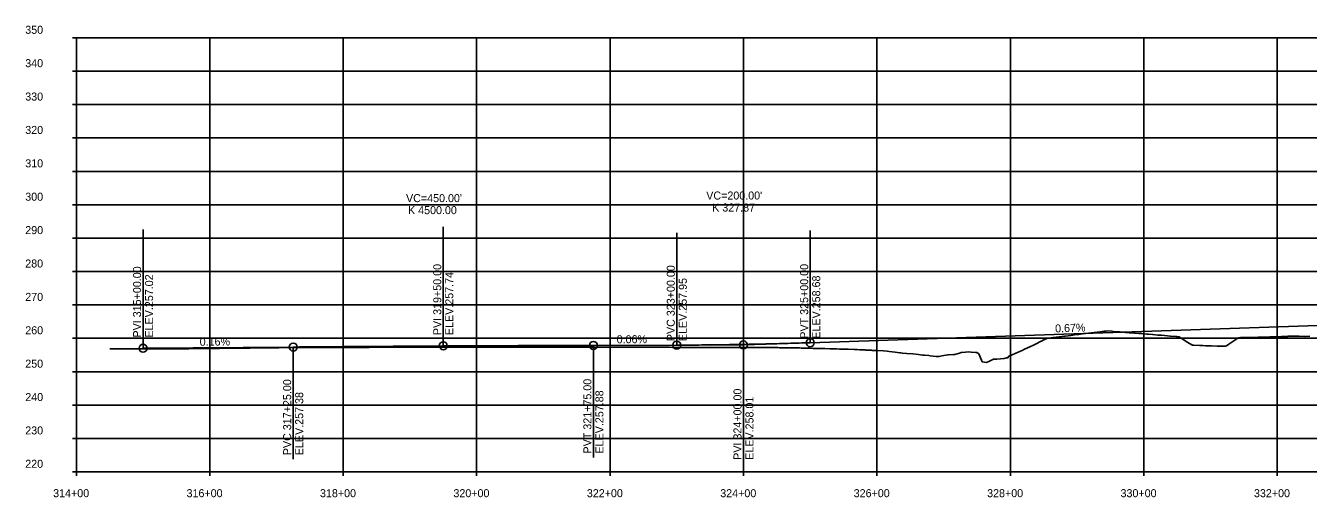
# Model space of a CAD drawing. Extents: x 880555 to 887700, y 1561392 to 1563161.
# Drawn here: x 880555 to 882477, y 1562454 to 1563161 of the extents above; entities that cross this region are included whole.
import ezdxf

# ---------------------------------------------------------------- set-up
doc = ezdxf.new("R2010")
doc.units = 0
for name, color, linetype in [('1', 7, 'Continuous'), ('30', 7, 'Continuous'), ('37', 7, 'Continuous'), ('56', 7, 'Continuous'), ('63', 7, 'Continuous'), ('R_Exist Surface', 7, 'Continuous')]:
    doc.layers.add(name, color=color, linetype=linetype)

msp = doc.modelspace()

# ---------------------------------------------------------------- linework, layer by layer
at = {"layer": '1'}
for p, q in [((881068.1, 1562680.4), (881180.6, 1562681.3)), ((881180.6, 1562681.3), (881293.1, 1562681.6)), ((881580.6, 1562682.5), (881630.6, 1562682.6)), ((881630.6, 1562682.6), (881680.6, 1562684.3))]:
    msp.add_line(p, q, dxfattribs=at)
at = {"layer": '37'}
for p, q in [((880624.6, 1563142.6), (880630.6, 1563142.6)), ((880624.6, 1563142.6), (880630.6, 1563142.6)), ((880630.6, 1562492.6), (880630.6, 1563142.6)), ((880630.6, 1563142.6), (887630.6, 1563142.6)), ((880630.6, 1563142.6), (887630.6, 1563142.6)), ((880830.6, 1562492.6), (880830.6, 1563142.6)), ((881030.6, 1562492.6), (881030.6, 1563142.6)), ((881230.6, 1562492.6), (881230.6, 1563142.6)), ((881430.6, 1562492.6), (881430.6, 1563142.6)), ((881630.6, 1562492.6), (881630.6, 1563142.6)), ((881830.6, 1562492.6), (881830.6, 1563142.6)), ((882030.6, 1562492.6), (882030.6, 1563142.6)), ((882230.6, 1562492.6), (882230.6, 1563142.6)), ((882430.6, 1562492.6), (882430.6, 1563142.6)), ((880624.6, 1563092.6), (880630.6, 1563092.6)), ((880630.6, 1563092.6), (887630.6, 1563092.6)), ((880624.6, 1563042.6), (880630.6, 1563042.6)), ((880630.6, 1563042.6), (887630.6, 1563042.6)), ((880624.6, 1562992.6), (880630.6, 1562992.6)), ((880630.6, 1562992.6), (887630.6, 1562992.6)), ((880624.6, 1562942.6), (880630.6, 1562942.6)), ((880630.6, 1562942.6), (887630.6, 1562942.6)), ((880624.6, 1562892.6), (880630.6, 1562892.6)), ((880630.6, 1562892.6), (887630.6, 1562892.6)), ((880624.6, 1562842.6), (880630.6, 1562842.6)), ((880630.6, 1562842.6), (887630.6, 1562842.6)), ((880624.6, 1562792.6), (880630.6, 1562792.6)), ((880630.6, 1562792.6), (887630.6, 1562792.6)), ((880624.6, 1562742.6), (880630.6, 1562742.6)), ((880630.6, 1562742.6), (887630.6, 1562742.6)), ((880624.6, 1562692.6), (880630.6, 1562692.6)), ((880630.6, 1562692.6), (887630.6, 1562692.6)), ((880624.6, 1562642.6), (880630.6, 1562642.6)), ((880630.6, 1562642.6), (887630.6, 1562642.6)), ((880624.6, 1562592.6), (880630.6, 1562592.6)), ((880630.6, 1562592.6), (887630.6, 1562592.6)), ((880624.6, 1562542.6), (880630.6, 1562542.6)), ((880630.6, 1562542.6), (887630.6, 1562542.6)), ((880624.6, 1562492.6), (880630.6, 1562492.6)), ((880630.6, 1562492.6), (887630.6, 1562492.6)), ((880630.6, 1562486.6), (880630.6, 1562492.6)), ((880830.6, 1562486.6), (880830.6, 1562492.6)), ((881030.6, 1562486.6), (881030.6, 1562492.6)), ((881230.6, 1562486.6), (881230.6, 1562492.6)), ((881430.6, 1562486.6), (881430.6, 1562492.6)), ((881630.6, 1562486.6), (881630.6, 1562492.6)), ((881830.6, 1562486.6), (881830.6, 1562492.6)), ((882030.6, 1562486.6), (882030.6, 1562492.6)), ((882230.6, 1562486.6), (882230.6, 1562492.6)), ((882430.6, 1562486.6), (882430.6, 1562492.6))]:
    msp.add_line(p, q, dxfattribs=at)
at = {"layer": '56'}
for p, q in [((880730.6, 1562687.7), (880730.6, 1562855.7)), ((881180.6, 1562691.3), (881180.6, 1562859.3)), ((881530.6, 1562682.3), (881530.6, 1562850.3)), ((881730.6, 1562686), (881730.6, 1562854)), ((881730.6, 1562686), (882520.6, 1562712.5)), ((880730.6, 1562677.7), (880730.6, 1562687.7)), ((880730.6, 1562677.7), (880955.6, 1562679.5)), ((880955.6, 1562679.5), (880955.6, 1562511.5)), ((881180.6, 1562681.3), (881180.6, 1562691.3)), ((881405.6, 1562682), (881530.6, 1562682.3)), ((881405.6, 1562682), (881405.6, 1562514)), ((881630.6, 1562682.6), (881630.6, 1562672.6)), ((881630.6, 1562672.6), (881630.6, 1562504.6))]:
    msp.add_line(p, q, dxfattribs=at)
for points in [[(880955.6, 1562679.5), (880965, 1562679.6), (880974.4, 1562679.6), (880983.7, 1562679.7), (880993.1, 1562679.8), (881002.5, 1562679.9), (881011.9, 1562679.9), (881021.2, 1562680), (881030.6, 1562680.1), (881040, 1562680.1), (881049.4, 1562680.2), (881058.7, 1562680.3), (881068.1, 1562680.3), (881077.5, 1562680.4), (881086.9, 1562680.4), (881096.2, 1562680.5), (881105.6, 1562680.6), (881115, 1562680.6), (881124.4, 1562680.7), (881133.7, 1562680.7), (881143.1, 1562680.8), (881152.5, 1562680.9), (881161.9, 1562680.9), (881171.2, 1562681), (881190, 1562681.1), (881199.4, 1562681.1), (881208.7, 1562681.2), (881218.1, 1562681.2), (881227.5, 1562681.3), (881236.9, 1562681.3), (881246.2, 1562681.3), (881255.6, 1562681.4), (881265, 1562681.4), (881274.4, 1562681.5), (881283.7, 1562681.5), (881293.1, 1562681.6), (881302.5, 1562681.6), (881311.9, 1562681.6), (881321.2, 1562681.7), (881330.6, 1562681.7), (881340, 1562681.7), (881349.4, 1562681.8), (881358.7, 1562681.8), (881368.1, 1562681.8), (881377.5, 1562681.9), (881386.9, 1562681.9), (881396.2, 1562681.9), (881405.6, 1562682)], [(881530.6, 1562682.3), (881534.8, 1562682.4), (881538.9, 1562682.4), (881543.1, 1562682.4), (881547.3, 1562682.4), (881551.4, 1562682.4), (881555.6, 1562682.5), (881559.8, 1562682.5), (881563.9, 1562682.5), (881568.1, 1562682.6), (881572.3, 1562682.6), (881576.4, 1562682.6), (881580.6, 1562682.7), (881584.8, 1562682.7), (881588.9, 1562682.8), (881593.1, 1562682.8), (881597.3, 1562682.9), (881601.4, 1562682.9), (881605.6, 1562683), (881609.8, 1562683.1), (881613.9, 1562683.1), (881618.1, 1562683.2), (881622.3, 1562683.3), (881626.4, 1562683.3), (881634.8, 1562683.5), (881638.9, 1562683.6), (881643.1, 1562683.6), (881647.3, 1562683.7), (881651.4, 1562683.8), (881655.6, 1562683.9), (881659.8, 1562684), (881663.9, 1562684.1), (881668.1, 1562684.2), (881672.3, 1562684.3), (881676.4, 1562684.4), (881680.6, 1562684.5), (881684.8, 1562684.6), (881688.9, 1562684.7), (881693.1, 1562684.8), (881697.3, 1562685), (881701.4, 1562685.1), (881705.6, 1562685.2), (881709.8, 1562685.3), (881713.9, 1562685.5), (881718.1, 1562685.6), (881722.3, 1562685.7), (881726.4, 1562685.9), (881730.6, 1562686)]]:
    msp.add_lwpolyline(points, dxfattribs=at)
for centre in [(880730.6, 1562677.7), (880955.6, 1562679.5), (881180.6, 1562681.3), (881405.6, 1562682), (881530.6, 1562682.3), (881630.6, 1562682.6), (881730.6, 1562686)]:
    msp.add_circle(centre, 6, dxfattribs=at)
at = {"layer": 'R_Exist Surface'}
msp.add_lwpolyline([(880680.6, 1562676.7), (880693.7, 1562676.7), (880694.3, 1562676.7), (880694.3, 1562676.7), (880697.4, 1562676.7), (880707.8, 1562676.8), (880709.1, 1562676.8), (880709.3, 1562676.8), (880709.3, 1562676.8), (880710, 1562676.8), (880724.3, 1562676.9), (880724.3, 1562676.9), (880731.2, 1562676.9), (880739.3, 1562676.8), (880739.3, 1562676.8), (880740.7, 1562676.9), (880754.3, 1562676.9), (880754.3, 1562676.9), (880767.7, 1562676.9), (880769.3, 1562676.9), (880769.8, 1562676.9), (880784.3, 1562676.8), (880784.3, 1562676.8), (880798.7, 1562676.9), (880799.3, 1562676.9), (880813.6, 1562677.1), (880814.3, 1562677.1), (880828.1, 1562677.3), (880829.3, 1562677.3), (880829.3, 1562677.3), (880843.7, 1562677.4), (880844.3, 1562677.4), (880845.2, 1562677.4), (880859.3, 1562677.6), (880859.5, 1562677.6), (880874.3, 1562677.8), (880874.3, 1562677.8), (880888.6, 1562677.9), (880889.3, 1562677.9), (880889.3, 1562677.9), (880890, 1562677.9), (880891.3, 1562677.9), (880904.3, 1562678.1), (880904.3, 1562678.1), (880914.2, 1562678.3), (880919.3, 1562678.3), (880919.3, 1562678.3), (880926.9, 1562678.4), (880934.3, 1562678.5), (880934.3, 1562678.5), (880934.6, 1562678.6), (880949.3, 1562678.8), (880949.9, 1562678.8), (880964.3, 1562678.8), (880964.3, 1562678.8), (880977.2, 1562678.9), (880979.3, 1562678.9), (880979.3, 1562678.9), (880993.7, 1562679), (880994.3, 1562679), (881008.8, 1562678.9), (881009.3, 1562678.9), (881009.8, 1562678.9), (881024.3, 1562678.9), (881024.3, 1562678.9), (881026.1, 1562678.9), (881039.3, 1562679), (881040.5, 1562679), (881054.3, 1562678.9), (881054.3, 1562678.9), (881060.7, 1562679), (881069.3, 1562679), (881069.3, 1562679), (881077.4, 1562679.1), (881084.3, 1562679.2), (881084.3, 1562679.2), (881090.6, 1562679.3), (881099.3, 1562679.3), (881101.4, 1562679.3), (881114.3, 1562679.4), (881114.3, 1562679.4), (881119.3, 1562679.4), (881129.3, 1562679.4), (881129.3, 1562679.4), (881132.4, 1562679.4), (881144.3, 1562679.3), (881144.3, 1562679.4), (881157.5, 1562679.4), (881159.3, 1562679.4), (881164.2, 1562679.3), (881165.8, 1562679.3), (881173, 1562679.3), (881174.4, 1562679.3), (881174.4, 1562679.3), (881181.8, 1562679.3), (881187.2, 1562679.3), (881189.4, 1562679.3), (881189.4, 1562679.3), (881190.5, 1562679.3), (881191.1, 1562679.3), (881199.3, 1562679.3), (881204.4, 1562679.3), (881204.4, 1562679.3), (881206.5, 1562679.3), (881208.1, 1562679.3), (881211.8, 1562679.3), (881216.9, 1562679.4), (881219.4, 1562679.4), (881225.7, 1562679.4), (881231, 1562679.4), (881234.4, 1562679.4), (881234.4, 1562679.4), (881235.9, 1562679.4), (881243.2, 1562679.4), (881249.4, 1562679.5), (881252, 1562679.5), (881258.9, 1562679.5), (881260.8, 1562679.5), (881264.5, 1562679.5), (881269.6, 1562679.4), (881271.3, 1562679.4), (881278.3, 1562679.5), (881279.5, 1562679.5), (881279.5, 1562679.5), (881286.2, 1562679.4), (881287.1, 1562679.4), (881294.5, 1562679.4), (881295.9, 1562679.4), (881304.7, 1562679.3), (881306.5, 1562679.3), (881309.5, 1562679.3), (881309.5, 1562679.3), (881312.4, 1562679.2), (881313.5, 1562679.2), (881322.2, 1562679.2), (881324.5, 1562679.2), (881326.2, 1562679.2), (881331, 1562679.1), (881339.5, 1562679.1), (881339.8, 1562679.1), (881348.6, 1562679.2), (881351.9, 1562679.2), (881354.6, 1562679.2), (881357.4, 1562679.2), (881357.5, 1562679.2), (881366.1, 1562679.2), (881369.6, 1562679.2), (881373.3, 1562679.2), (881374.9, 1562679.3), (881383.7, 1562679.3), (881384.6, 1562679.3), (881392.5, 1562679.3), (881399, 1562679.3), (881399.6, 1562679.3), (881400.3, 1562679.3), (881401.3, 1562679.3), (881410, 1562679.2), (881414.7, 1562679.2), (881418.8, 1562679.2), (881421.6, 1562679.2), (881427.6, 1562679.3), (881429.7, 1562679.3), (881436.4, 1562679.3), (881437.2, 1562679.3), (881444.7, 1562679.3), (881445.2, 1562679.3), (881453.9, 1562679.3), (881458.3, 1562679.3), (881459.7, 1562679.3), (881460.9, 1562679.3), (881462.7, 1562679.3), (881471.5, 1562679.3), (881474.7, 1562679.3), (881480.3, 1562679.3), (881489.1, 1562679.2), (881489.1, 1562679.2), (881489.7, 1562679.2), (881490, 1562679.2), (881497.8, 1562679.2), (881504.7, 1562679.2), (881505, 1562679.2), (881505.5, 1562679.2), (881506.6, 1562679.2), (881514.5, 1562679.1), (881515.4, 1562679.1), (881519.7, 1562679.1), (881524.2, 1562679), (881530.3, 1562679), (881533, 1562679), (881534.7, 1562679), (881541.7, 1562679), (881545.6, 1562679), (881549.7, 1562679), (881550.5, 1562679), (881551, 1562679), (881553.8, 1562679), (881559.3, 1562678.9), (881564.7, 1562678.8), (881564.7, 1562678.8), (881567.5, 1562678.8), (881568.1, 1562678.8), (881570.3, 1562678.8), (881572.7, 1562678.8), (881574.6, 1562678.8), (881576.9, 1562678.8), (881579.8, 1562678.9), (881585.6, 1562678.9), (881588.5, 1562678.9), (881594.4, 1562678.9), (881594.8, 1562678.9), (881603.2, 1562678.9), (881606.2, 1562678.9), (881609.7, 1562678.8), (881612, 1562678.8), (881614, 1562678.8), (881620.8, 1562678.7), (881624.7, 1562678.7), (881627.8, 1562678.7), (881629.5, 1562678.7), (881638.3, 1562678.7), (881639.8, 1562678.8), (881647.1, 1562678.7), (881650.9, 1562678.7), (881654.8, 1562678.7), (881655.9, 1562678.7), (881661.3, 1562678.7), (881664.7, 1562678.7), (881669.8, 1562678.6), (881673.4, 1562678.6), (881676.1, 1562678.6), (881682.2, 1562678.6), (881684.8, 1562678.5), (881691, 1562678.5), (881694.3, 1562678.4), (881699.6, 1562678.3), (881699.8, 1562678.3), (881703.3, 1562678.3), (881708.6, 1562678.2), (881714.6, 1562678.1), (881717.3, 1562678), (881722.5, 1562677.9), (881726.1, 1562677.8), (881729.7, 1562677.6), (881734.9, 1562677.5), (881736.3, 1562677.5), (881743.7, 1562677.4), (881744.7, 1562677.4), (881749.6, 1562677.2), (881752.5, 1562677.1), (881759.8, 1562676.8), (881761.2, 1562676.7), (881769.3, 1562676.6), (881770, 1562676.6), (881774.5, 1562676.5), (881778.8, 1562676.4), (881785.7, 1562676.1), (881787.6, 1562676.1), (881796.4, 1562675.7), (881800.8, 1562675.6), (881805.1, 1562675.4), (881812.3, 1562675.1), (881813.9, 1562675), (881819.1, 1562674.8), (881822.7, 1562674.6), (881823.6, 1562674.5), (881826.9, 1562674.4), (881831.5, 1562674.2), (881840.3, 1562673.7), (881846, 1562673.4), (881849, 1562673), (881857.8, 1562671.8), (881864.8, 1562670.8), (881866.6, 1562670.7), (881868.8, 1562670.5), (881875.2, 1562670), (881875.4, 1562669.9), (881884.2, 1562669.1), (881892.9, 1562668.1), (881898.8, 1562667.5), (881901.7, 1562667.2), (881908.4, 1562666.6), (881910.5, 1562666.4), (881919.3, 1562665.5), (881920.5, 1562665.4), (881923.7, 1562665.1), (881924, 1562665.2), (881925.8, 1562665.6), (881928.1, 1562666.1), (881936.8, 1562667.8), (881937.9, 1562668), (881945.6, 1562668.5), (881945.6, 1562668.5), (881947.2, 1562668.5), (881950.8, 1562669.4), (881954.4, 1562670.5), (881956.8, 1562671.3), (881957.7, 1562671.4), (881963.2, 1562671.9), (881967.4, 1562672.3), (881972, 1562671.9), (881978.7, 1562671.3), (881980.5, 1562671.3), (881980.7, 1562671.1), (881981, 1562670.9), (881982.8, 1562669.8), (881984.9, 1562666.5), (881985, 1562666.3), (881985.1, 1562666.3), (881985.1, 1562666), (881985.1, 1562666), (881988.6, 1562657.5), (881989.5, 1562657.3), (881994.6, 1562656.1), (881996, 1562656.8), (881998.3, 1562657.8), (882005.5, 1562661.1), (882007.1, 1562661.2), (882010.2, 1562661.4), (882015.9, 1562662), (882021.3, 1562662.5), (882024.6, 1562663.1), (882026.9, 1562663.5), (882027.9, 1562665.4), (882033.4, 1562667.8), (882042.2, 1562671.7), (882045, 1562672.9), (882049.4, 1562675), (882051, 1562675.7), (882056.4, 1562678.2), (882059.8, 1562679.8), (882066.4, 1562683), (882068.5, 1562684), (882076.8, 1562688.1), (882077.3, 1562688.4), (882079.8, 1562689.6), (882086.1, 1562692.8), (882086.1, 1562692.8), (882091.9, 1562693.2), (882092.3, 1562693.2), (882094.9, 1562693.6), (882103.7, 1562694.8), (882111.8, 1562695.9), (882112.4, 1562695.9), (882113.1, 1562695.9), (882121.2, 1562696.9), (882130, 1562698.1), (882130, 1562698.1), (882133.1, 1562698.4), (882136, 1562698.7), (882138.8, 1562699.1), (882147.6, 1562700.2), (882152.5, 1562700.8), (882156.2, 1562701.2), (882156.3, 1562701.2), (882165.1, 1562702.3), (882171.4, 1562703.1), (882173.9, 1562703.4), (882175.9, 1562703.6), (882182.7, 1562703.1), (882185.4, 1562702.9), (882189.6, 1562702.5), (882191.5, 1562702.4), (882194.4, 1562702.1), (882200.2, 1562701.7), (882203.2, 1562701.5), (882208.8, 1562701), (882209, 1562701), (882216.8, 1562700.4), (882217.8, 1562700.3), (882223.2, 1562699.8), (882226.6, 1562699.6), (882230.3, 1562699.3), (882235.4, 1562698.9), (882237.5, 1562698.7), (882243.7, 1562698.2), (882244.1, 1562698.2), (882251.8, 1562697.5), (882252.9, 1562697.4), (882257.1, 1562697.1), (882261.7, 1562696.7), (882266.1, 1562696.3), (882270.3, 1562696), (882270.5, 1562696), (882279.3, 1562695.2), (882280.4, 1562695.2), (882283.5, 1562694.9), (882288, 1562692), (882296.8, 1562686.5), (882302.8, 1562682.7), (882303.7, 1562682.5), (882304.6, 1562682.3), (882305.6, 1562682.2), (882314.4, 1562681.8), (882319, 1562681.6), (882323.2, 1562681.5), (882328.7, 1562681.2), (882329.1, 1562681.3), (882329.6, 1562681.3), (882331.9, 1562681.2), (882340.7, 1562680.9), (882349.5, 1562680.7), (882352.8, 1562680.6), (882354.4, 1562681.4), (882358.3, 1562683.9), (882367.1, 1562689.7), (882371.7, 1562692.8), (882373.1, 1562693.5), (882375.6, 1562693.6), (882375.8, 1562693.6), (882384.6, 1562693.7), (882393.4, 1562693.8), (882393.4, 1562693.8), (882398.9, 1562694), (882402.2, 1562694.1), (882411, 1562694.2), (882413.9, 1562694.3), (882419.7, 1562694.6), (882422.7, 1562694.7), (882428.5, 1562694.8), (882434.7, 1562694.9), (882437.3, 1562695.1), (882446.1, 1562695.5), (882447, 1562695.6), (882454.9, 1562695.8), (882455.8, 1562695.8), (882463.6, 1562695.7), (882472.2, 1562695.5), (882472.4, 1562695.5), (882479.4, 1562695.7)], dxfattribs=at)

# ---------------------------------------------------------------- texts
at = {"layer": '30'}
for s, p in [('350', (880554, 1563148.6)), ('350', (880554, 1563148.6)), ('340', (880554, 1563098.6)), ('330', (880554, 1563048.6)), ('320', (880554, 1562998.6)), ('310', (880554, 1562948.6)), ('300', (880554, 1562898.6)), ('290', (880554, 1562848.6)), ('280', (880554, 1562798.6)), ('270', (880554, 1562748.6)), ('260', (880554, 1562698.6)), ('250', (880554, 1562648.6)), ('240', (880554, 1562598.6)), ('230', (880554, 1562548.6)), ('220', (880554, 1562498.6)), ('314+00', (880595.8, 1562454.6)), ('316+00', (880795.8, 1562454.6)), ('318+00', (880995.8, 1562454.6)), ('320+00', (881195.8, 1562454.6)), ('322+00', (881395.8, 1562454.6)), ('324+00', (881595.8, 1562454.6)), ('326+00', (881795.8, 1562454.6)), ('328+00', (881995.8, 1562454.6)), ('330+00', (882195.8, 1562454.6)), ('332+00', (882395.8, 1562454.6))]:
    msp.add_text(s, height=12, dxfattribs=at).set_placement(p)
at = {"layer": '56'}
for s, p in [("VC=450.00'", (881124.8, 1562896.5)), ("VC=200.00'", (881574.8, 1562900.4)), ('K 4500.00', (881127.8, 1562878.5)), ('K 327.87', (881583.7, 1562882.4))]:
    msp.add_text(s, height=12, dxfattribs=at).set_placement(p)
for s, rotation, p in [('PVI 315+00.00', 90, (880727.6, 1562693.7)), ('PVI 319+50.00', 90, (881177.6, 1562697.3)), ('ELEV.257.74', 90, (881195.6, 1562697.3)), ('PVC 323+00.00', 90, (881527.6, 1562688.3)), ('PVT 325+00.00', 90, (881727.6, 1562692)), ('ELEV.257.02', 90, (880745.6, 1562693.7)), ('ELEV.257.95', 90, (881545.6, 1562688.3)), ('ELEV.258.68', 90, (881745.6, 1562692)), ('0.67%', 1.9187, (882097.9, 1562701.3)), ('0.16%', 0.4584, (880815.5, 1562681.4)), ('0.06%', 0.1719, (881440.5, 1562685.1)), ('PVC 317+25.00', 90, (880952.6, 1562517.5)), ('PVT 321+75.00', 90, (881402.6, 1562520)), ('ELEV.257.38', 90, (880970.6, 1562517.5)), ('ELEV.257.88', 90, (881420.6, 1562520)), ('PVI 324+00.00', 90, (881627.6, 1562510.6)), ('ELEV.258.01', 90, (881645.6, 1562510.6))]:
    msp.add_text(s, height=12, rotation=rotation, dxfattribs=at).set_placement(p)
at = {"layer": '63'}
msp.add_text('-', height=0.0001, dxfattribs=at).set_placement((880630.6, 1562492.6))

doc.saveas('drawing.dxf')
